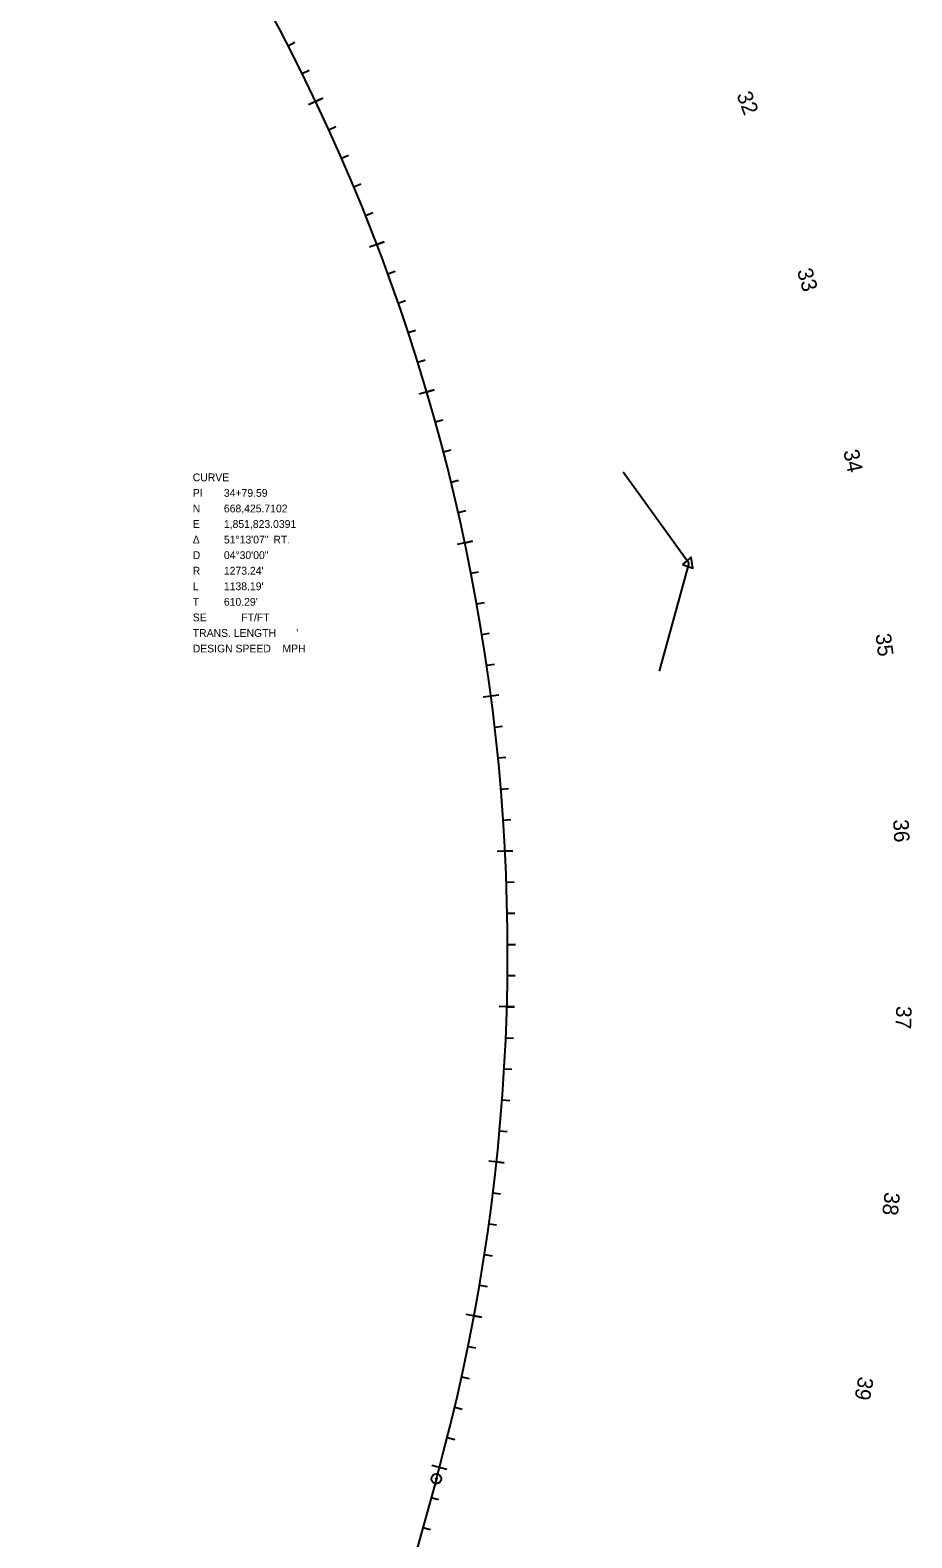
# Model space of a CAD drawing. Extents: x 1849564 to 1851966, y 666816 to 670715.
# Drawn here: x 1851400 to 1851966, y 667799 to 668768 of the extents above; entities that cross this region are included whole.
import ezdxf

# ---------------------------------------------------------------- set-up
doc = ezdxf.new("R2010")
doc.units = 0
for name, color, linetype in [('CONCEPT - PAVEMENT MARKING - Crosswalk Long', 7, 'Continuous'), ('CONCEPT - PAVEMENT MARKING - Crosswalk Parallel', 7, 'Continuous'), ('CONCEPT - PAVEMENT MARKING - Stop Bar', 7, 'Continuous'), ('CONCEPT - PAVEMENT MARKING - Striping - Yellow', 7, 'Continuous'), ('Default', 7, 'Continuous'), ('DES - DRG - Special Ditches', 7, 'Continuous')]:
    doc.layers.add(name, color=color, linetype=linetype)

msp = doc.modelspace()

# ---------------------------------------------------------------- linework, layer by layer
at = {"layer": 'CONCEPT - PAVEMENT MARKING - Crosswalk Parallel'}
for q in [(1851780.91, 668484.1), (1851803.91, 668356.3), (1851823.04, 668425.71)]:
    msp.add_line((1851823.04, 668425.71), q, dxfattribs=at)
msp.add_lwpolyline([(1851818.95, 668424.97), (1851825.72, 668422.54), (1851824.45, 668429.62)], close=True, dxfattribs=at)
at = {"layer": 'CONCEPT - PAVEMENT MARKING - Stop Bar'}
for p, q in [((1851565.58, 668758.23), (1851570.01, 668760.51)), ((1851574.59, 668740.37), (1851579.05, 668742.58)), ((1851587.83, 668724.52), (1851578.8, 668720.23)), ((1851591.76, 668704.25), (1851596.29, 668706.32)), ((1851599.92, 668685.99), (1851604.48, 668687.98)), ((1851607.79, 668667.6), (1851612.39, 668669.53)), ((1851615.37, 668649.1), (1851620, 668650.95)), ((1851627.33, 668632.26), (1851617.99, 668628.69)), ((1851629.66, 668611.73), (1851634.34, 668613.44)), ((1851636.36, 668592.89), (1851641.06, 668594.52)), ((1851642.76, 668573.94), (1851647.49, 668575.5)), ((1851648.87, 668554.9), (1851653.62, 668556.38)), ((1851659.47, 668537.17), (1851649.88, 668534.35)), ((1851660.18, 668516.53), (1851664.98, 668517.87)), ((1851665.38, 668497.22), (1851670.2, 668498.48)), ((1851670.28, 668477.83), (1851675.12, 668479.01)), ((1851674.87, 668458.37), (1851679.73, 668459.47)), ((1851684.05, 668439.86), (1851674.27, 668437.8)), ((1851683.14, 668419.23), (1851688.02, 668420.18)), ((1851686.81, 668399.57), (1851691.71, 668400.45)), ((1851690.17, 668379.86), (1851695.08, 668380.65)), ((1851693.22, 668360.09), (1851698.15, 668360.81)), ((1851700.92, 668340.92), (1851691, 668339.63)), ((1851698.39, 668320.43), (1851703.34, 668320.99)), ((1851700.51, 668300.54), (1851705.46, 668301.03)), ((1851702.31, 668280.62), (1851707.27, 668281.03)), ((1851703.8, 668260.68), (1851708.77, 668261.01)), ((1851709.97, 668240.97), (1851699.98, 668240.46)), ((1851705.84, 668220.73), (1851710.82, 668220.91)), ((1851706.39, 668200.74), (1851711.37, 668200.84)), ((1851706.63, 668180.74), (1851711.61, 668180.76)), ((1851706.55, 668160.74), (1851711.53, 668160.68)), ((1851711.15, 668140.61), (1851701.16, 668140.88)), ((1851705.45, 668120.76), (1851710.43, 668120.54)), ((1851704.43, 668100.78), (1851709.4, 668100.49)), ((1851703.1, 668080.83), (1851708.06, 668080.46)), ((1851701.45, 668060.9), (1851706.41, 668060.45)), ((1851704.46, 668040.46), (1851694.52, 668041.52)), ((1851697.22, 668021.12), (1851702.16, 668020.52)), ((1851694.63, 668001.29), (1851699.56, 668000.61)), ((1851691.74, 667981.5), (1851696.66, 667980.74)), ((1851688.53, 667961.76), (1851693.44, 667960.92)), ((1851689.93, 667941.15), (1851680.1, 667942.99)), ((1851681.19, 667922.44), (1851686.07, 667921.45)), ((1851677.06, 667902.87), (1851681.92, 667901.81)), ((1851672.62, 667883.37), (1851677.46, 667882.23)), ((1851667.87, 667863.94), (1851672.7, 667862.72)), ((1851667.65, 667843.29), (1851657.99, 667845.89)), ((1851657.53, 667825.3), (1851662.33, 667823.98)), ((1851652.21, 667806.02), (1851657.02, 667804.7))]:
    msp.add_line(p, q, dxfattribs=at)
at = {"layer": 'CONCEPT - PAVEMENT MARKING - Striping - Yellow'}
for p, q in [((1851583.32, 668722.38), (1851587.82, 668724.52)), ((1851622.66, 668630.47), (1851627.31, 668632.25)), ((1851654.67, 668535.76), (1851659.45, 668537.17)), ((1851679.16, 668438.83), (1851684.03, 668439.86)), ((1851700.92, 668340.92), (1851690.98, 668339.63)), ((1851704.98, 668240.71), (1851709.95, 668240.97)), ((1851706.16, 668140.74), (1851711.13, 668140.61)), ((1851699.49, 668040.99), (1851704.44, 668040.47)), ((1851685.01, 667942.07), (1851689.91, 667941.16)), ((1851667.65, 667843.29), (1851657.98, 667845.9))]:
    msp.add_line(p, q, dxfattribs=at)
for radius in [3.14, 0.33]:
    msp.add_circle((1851660.85, 667837.37), radius, dxfattribs=at)
at = {"layer": 'Default'}
msp.add_line((1851660.85, 667837.37), (1851399.91, 666890.78), dxfattribs=at)
msp.add_arc((1850433.4, 668175.73), 1273.24, 344.58842, 35.80713, dxfattribs=at)
at = {"layer": 'DES - DRG - Special Ditches'}
msp.add_line((1851660.85, 667837.37), (1851399.91, 666890.78), dxfattribs=at)
msp.add_arc((1850433.4, 668175.73), 1273.24, 344.58842, 35.80713, dxfattribs=at)

# ---------------------------------------------------------------- texts
at = {"layer": 'CONCEPT - PAVEMENT MARKING - Crosswalk Long'}
for s, p in [('CURVE    ', (1851504.37, 668478.38)), ('PI', (1851504.37, 668468.38)), ('34+79.59', (1851524.37, 668468.38)), ('N', (1851504.37, 668458.38)), ('668,425.7102', (1851524.37, 668458.38)), ('E', (1851504.37, 668448.38)), ('1,851,823.0391', (1851524.37, 668448.38)), ('Δ', (1851504.37, 668438.38)), ('51°13\'07"', (1851524.37, 668438.38)), (' RT.', (1851554.28, 668438.38)), ('D', (1851504.37, 668428.38)), ('04°30\'00"', (1851524.37, 668428.38)), ('R', (1851504.37, 668418.38)), ("1273.24'", (1851524.37, 668418.38)), ('L', (1851504.37, 668408.38)), ("1138.19'", (1851524.37, 668408.38)), ('T', (1851504.37, 668398.38)), ("610.29'", (1851524.37, 668398.38)), ('SE', (1851504.37, 668388.38)), ('      FT/FT', (1851524.37, 668388.38)), ("TRANS. LENGTH       '", (1851504.37, 668378.38)), ('DESIGN SPEED    MPH', (1851504.37, 668368.38))]:
    msp.add_text(s, height=5, dxfattribs=at).set_placement(p)
at = {"layer": 'CONCEPT - PAVEMENT MARKING - Stop Bar'}
for s, rotation, p in [('32', 290.92544, (1851853.54, 668726.64)), ('33', 286.42544, (1851892.37, 668613.57)), ('34', 281.92544, (1851922.23, 668497.73)), ('35', 277.42544, (1851942.9, 668379.98)), ('36', 272.92544, (1851954.27, 668260.88)), ('37', 268.42545, (1851956.27, 668141.29)), ('38', 263.92545, (1851948.87, 668021.92)), ('39', 259.42545, (1851932.13, 667903.49))]:
    msp.add_text(s, height=9.96, rotation=rotation, dxfattribs=at).set_placement(p)
at = {"layer": 'CONCEPT - PAVEMENT MARKING - Striping - Yellow'}
msp.add_text('35', height=9.96, rotation=277.42544, dxfattribs=at).set_placement((1851942.9, 668379.98))

doc.saveas('drawing.dxf')
